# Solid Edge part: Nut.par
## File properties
Document Number: NutM15
Revision: A
File Size: 0
Number of Sheets: 0
Number of Objects: 0
Title: Nut
Author: jmrobins
Comments: Nut
Template: NORMAL.PAR
Last saved by: rkriggs
Revision: 59
Application: Solid Edge
Density: 0.00000847 kg/mm^3
Accuracy: 0.99
Material: Brass, yellow brass
Face Style: Brass
Fill Style: ANSI33(Brass)
Virtual Style: Polished brass
Coef. of Thermal Exp: 2e-05
Thermal Conductivity: 116.0
Specific Heat: 377.0
Modulus of Elasticity: 103421355000.0
Poission's Ratio: 0.32
Yield Stress: 413685420.0
Ultimate Stress: 510212018.0
Elongation: 0.0
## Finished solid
Body 1: solid body, 21 faces, 56 edges, 36 vertices.
  Faces by surface: cone 12, plane 8, cylinder 1
  Edges by curve: intersection 24, line 18, circle 14
Bounding box of the edges (mm): 27.713 x 24.000 x 7.500, from (-13.8564, -12, 0) to (13.8564, 12, 7.5).
Cylindrical faces by radius (mm): R7.5 x1
Conical faces (half-angle, radius in mm at the cone's reference point): 45 deg R10.8787 x6, 45 deg R15.1213 x6
Planar faces by outward normal: +y 1, +z 1, -y 1, -z 1, oblique 4
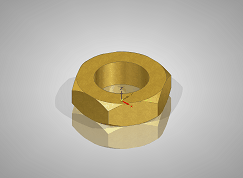
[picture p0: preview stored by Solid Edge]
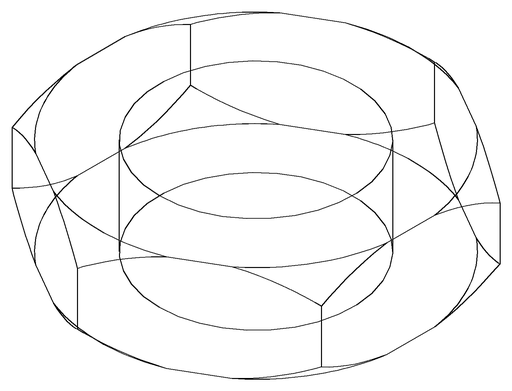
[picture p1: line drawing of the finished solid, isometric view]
